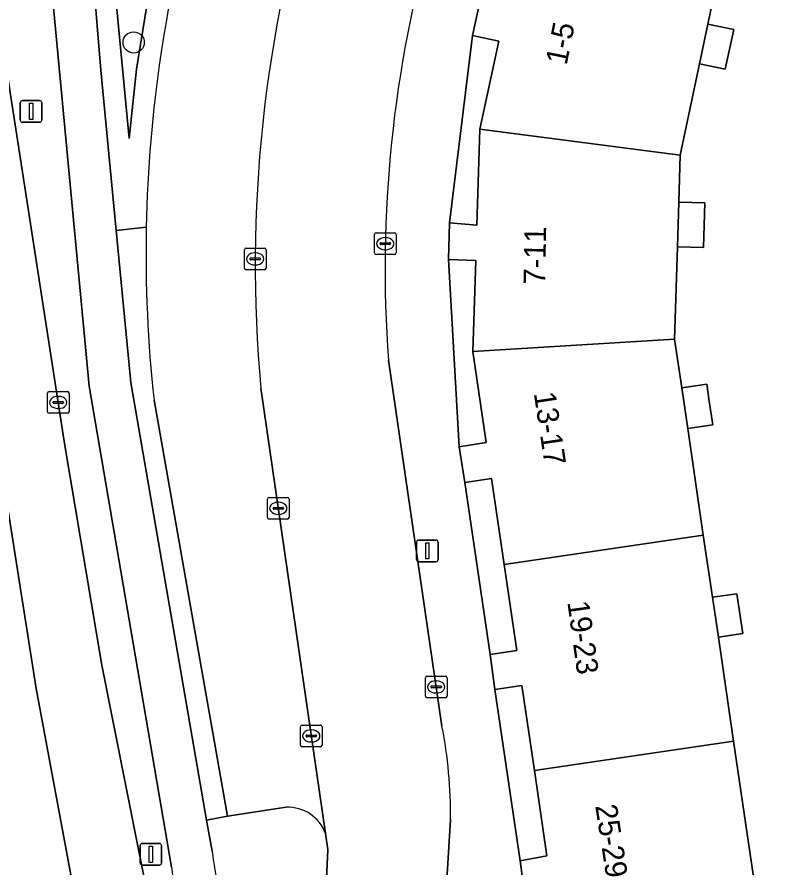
# Model space of a CAD drawing. Extents: x 159371 to 159986, y 382987 to 383597.
# Drawn here: x 159397.8 to 159432.71, y 383349.64 to 383388.85 of the extents above; entities that cross this region are included whole.
import ezdxf

# ---------------------------------------------------------------- set-up
doc = ezdxf.new("R2010")
doc.units = 0
for name, color, linetype in [('IMGEO_Boom', 7, 'Continuous'), ('IMGEO_Erf', 7, 'Continuous'), ('IMGEO_Fietspad_open', 7, 'Continuous'), ('IMGEO_Groenvoorziening', 7, 'Continuous'), ('IMGEO_Kolk', 7, 'Continuous'), ('IMGEO_Lichtmast', 7, 'Continuous'), ('IMGEO_Pand', 7, 'Continuous'), ('IMGEO_Pand_nummerreeks', 7, 'Continuous'), ('IMGEO_Parkeervlak_open', 7, 'Continuous'), ('IMGEO_Rijbaan_lokaal_open', 7, 'Continuous'), ('IMGEO_Rijbaan_regionaal_gesloten', 7, 'Continuous'), ('IMGEO_Verkeerseiland_groen', 7, 'Continuous'), ('IMGEO_Verkeerseiland_open', 7, 'Continuous'), ('IMGEO_Verkeersregelinstallatiepaal', 7, 'Continuous'), ('IMGEO_Voetpad_open', 7, 'Continuous')]:
    doc.layers.add(name, color=color, linetype=linetype)

msp = doc.modelspace()

# ---------------------------------------------------------------- linework, layer by layer
at = {"layer": 'IMGEO_Boom'}
msp.add_circle((159403.177, 383387.674), 0.489, dxfattribs=at)
at = {"layer": 'IMGEO_Erf'}
msp.add_lwpolyline([(159430.16, 383390.86), (159429.667, 383388.524), (159430.854, 383388.274), (159430.467, 383386.44), (159429.28, 383386.69), (159428.392, 383382.479), (159428.324, 383380.313), (159429.522, 383380.275), (159429.457, 383378.217), (159428.259, 383378.255), (159428.125, 383373.99), (159428.456, 383371.738), (159429.615, 383371.909), (159429.73, 383371.126), (159429.891, 383370.032), (159428.732, 383369.862), (159429.453, 383364.954), (159429.875, 383362.082), (159431.003, 383362.248), (159431.274, 383360.406), (159430.146, 383360.24), (159430.851, 383355.442), (159432.244, 383345.961), (159433.639, 383336.466)], dxfattribs=at)
at = {"layer": 'IMGEO_Fietspad_open'}
for points in [[(159398.117, 383396.756), (159399.119, 383392.769), (159399.173, 383392.556), (159401.123, 383371.822), (159404.915, 383349.644)], [(159406.791, 383350.369), (159406.542, 383351.805), (159403.042, 383371.984), (159402.373, 383379.003), (159401.668, 383386.401), (159400.956, 383394.962)]]:
    msp.add_lwpolyline(points, dxfattribs=at)
for centre, radius, start, end in [((159440.077, 383355.21), 33.636, 188.2744, 198.5159), ((159443.982, 383355.971), 39.576, 189.1999, 197.6695)]:
    msp.add_arc(centre, radius, start, end, dxfattribs=at)
at = {"layer": 'IMGEO_Groenvoorziening'}
msp.add_lwpolyline([(159419.94, 383400.506), (159420.009, 383400.664), (159408.921, 383404.193), (159405.054, 383399.714), (159400.956, 383394.962), (159401.668, 383386.401), (159402.373, 383379.003), (159403.759, 383379.151)], dxfattribs=at)
for points in [[(159417.737, 383398.308), (159418.48, 383399.91), (159409.013, 383402.804), (159401.894, 383394.566), (159402.974, 383383.238), (159403.31, 383386.448), (159403.787, 383389.376), (159404.473, 383392.564), (159406.076, 383398.462), (159416.727, 383395.545)], [(159406.076, 383398.462), (159404.473, 383392.564), (159403.787, 383389.376), (159403.31, 383386.448), (159402.974, 383383.238), (159401.894, 383394.566), (159409.013, 383402.804), (159418.48, 383399.91), (159417.737, 383398.308), (159416.727, 383395.545)]]:
    msp.add_lwpolyline(points, close=True, dxfattribs=at)
msp.add_arc((159465.951, 383377.929), 62.204, 164.11625, 178.874, dxfattribs=at)
at = {"layer": 'IMGEO_Kolk'}
for p, q in [((159414.283, 383377.967), (159414.283, 383378.819)), ((159414.358, 383378.893), (159415.21, 383378.893)), ((159414.771, 383378.673), (159414.796, 383378.673)), ((159415.284, 383378.819), (159415.284, 383377.967)), ((159408.359, 383378.19), (159409.211, 383378.19)), ((159414.542, 383378.387), (159414.542, 383378.399)), ((159414.98, 383378.35), (159414.582, 383378.35)), ((159414.585, 383378.436), (159414.983, 383378.436)), ((159415.026, 383378.399), (159415.026, 383378.387)), ((159408.284, 383377.264), (159408.284, 383378.116)), ((159408.772, 383377.97), (159408.797, 383377.97)), ((159409.285, 383378.116), (159409.285, 383377.264)), ((159415.21, 383377.893), (159414.358, 383377.893)), ((159414.794, 383378.113), (159414.769, 383378.113)), ((159408.543, 383377.684), (159408.543, 383377.696)), ((159408.981, 383377.647), (159408.583, 383377.647)), ((159408.586, 383377.733), (159408.984, 383377.733)), ((159408.795, 383377.41), (159408.77, 383377.41)), ((159409.027, 383377.696), (159409.027, 383377.684)), ((159409.211, 383377.19), (159408.359, 383377.19)), ((159399.197, 383370.645), (159399.197, 383371.497)), ((159399.272, 383371.571), (159400.124, 383371.571)), ((159400.198, 383371.497), (159400.198, 383370.645)), ((159399.499, 383371.114), (159399.897, 383371.114)), ((159399.685, 383371.351), (159399.71, 383371.351)), ((159399.456, 383371.065), (159399.456, 383371.077)), ((159399.894, 383371.028), (159399.496, 383371.028)), ((159399.708, 383370.791), (159399.683, 383370.791)), ((159399.94, 383371.077), (159399.94, 383371.065)), ((159400.124, 383370.571), (159399.272, 383370.571)), ((159409.347, 383365.763), (159409.347, 383366.615)), ((159409.422, 383366.689), (159410.274, 383366.689)), ((159409.835, 383366.469), (159409.86, 383366.469)), ((159410.348, 383366.615), (159410.348, 383365.763)), ((159409.606, 383366.183), (159409.606, 383366.195)), ((159410.044, 383366.146), (159409.646, 383366.146)), ((159409.649, 383366.232), (159410.047, 383366.232)), ((159410.09, 383366.195), (159410.09, 383366.183)), ((159410.274, 383365.689), (159409.422, 383365.689)), ((159409.858, 383365.909), (159409.833, 383365.909)), ((159416.633, 383357.524), (159416.633, 383358.376)), ((159416.708, 383358.45), (159417.56, 383358.45)), ((159417.121, 383358.23), (159417.146, 383358.23)), ((159417.634, 383358.376), (159417.634, 383357.524)), ((159416.892, 383357.944), (159416.892, 383357.956)), ((159417.33, 383357.907), (159416.932, 383357.907)), ((159416.935, 383357.993), (159417.333, 383357.993)), ((159417.376, 383357.956), (159417.376, 383357.944)), ((159417.56, 383357.45), (159416.708, 383357.45)), ((159417.144, 383357.67), (159417.119, 383357.67)), ((159410.869, 383355.263), (159410.869, 383356.115)), ((159410.944, 383356.189), (159411.796, 383356.189)), ((159411.357, 383355.969), (159411.382, 383355.969)), ((159411.87, 383356.115), (159411.87, 383355.263)), ((159411.128, 383355.683), (159411.128, 383355.695)), ((159411.566, 383355.646), (159411.168, 383355.646)), ((159411.171, 383355.732), (159411.569, 383355.732)), ((159411.612, 383355.695), (159411.612, 383355.683)), ((159411.796, 383355.189), (159410.944, 383355.189)), ((159411.38, 383355.409), (159411.355, 383355.409))]:
    msp.add_line(p, q, dxfattribs=at)
for points in [[(159414.283, 383377.967), (159414.283, 383378.819)], [(159414.358, 383378.893), (159415.21, 383378.893)], [(159415.284, 383378.819), (159415.284, 383377.967)], [(159408.359, 383378.19), (159409.211, 383378.19)], [(159408.284, 383377.264), (159408.284, 383378.116)], [(159409.285, 383378.116), (159409.285, 383377.264)], [(159415.21, 383377.893), (159414.358, 383377.893)], [(159409.211, 383377.19), (159408.359, 383377.19)], [(159399.197, 383370.645), (159399.197, 383371.497)], [(159399.272, 383371.571), (159400.124, 383371.571)], [(159400.198, 383371.497), (159400.198, 383370.645)], [(159400.124, 383370.571), (159399.272, 383370.571)], [(159409.347, 383365.763), (159409.347, 383366.615)], [(159409.422, 383366.689), (159410.274, 383366.689)], [(159410.348, 383366.615), (159410.348, 383365.763)], [(159410.274, 383365.689), (159409.422, 383365.689)], [(159416.633, 383357.524), (159416.633, 383358.376)], [(159416.708, 383358.45), (159417.56, 383358.45)], [(159417.634, 383358.376), (159417.634, 383357.524)], [(159417.56, 383357.45), (159416.708, 383357.45)], [(159410.869, 383355.263), (159410.869, 383356.115)], [(159410.944, 383356.189), (159411.796, 383356.189)], [(159411.87, 383356.115), (159411.87, 383355.263)], [(159411.796, 383355.189), (159410.944, 383355.189)]]:
    msp.add_lwpolyline(points, dxfattribs=at)
for centre, radius, start, end in [((159414.36, 383378.817), 0.0765, 91.552, 178.448), ((159414.36, 383378.817), 0.0765, 91.552, 178.448), ((159415.208, 383378.817), 0.0765, 1.552, 88.448), ((159415.208, 383378.817), 0.0765, 1.552, 88.448), ((159408.361, 383378.114), 0.0765, 91.552, 178.448), ((159408.361, 383378.114), 0.0765, 91.552, 178.448), ((159409.209, 383378.114), 0.0765, 1.552, 88.448), ((159409.209, 383378.114), 0.0765, 1.552, 88.448), ((159414.582, 383378.396), 0.0403, 85.8775, 175.7526), ((159414.579, 383378.386), 0.0366, 178.938, 274.7102), ((159414.983, 383378.393), 0.043, 264.8664, 352.4533), ((159414.987, 383378.398), 0.0386, 1.7309, 96.639), ((159414.36, 383377.969), 0.0765, 181.552, 268.448), ((159414.36, 383377.969), 0.0765, 181.552, 268.448), ((159415.208, 383377.969), 0.0765, 271.552, 358.448), ((159415.208, 383377.969), 0.0765, 271.552, 358.448), ((159408.583, 383377.693), 0.0403, 85.8775, 175.7526), ((159408.58, 383377.683), 0.0366, 178.938, 274.7102), ((159408.984, 383377.69), 0.043, 264.8664, 352.4533), ((159408.988, 383377.695), 0.0386, 1.7309, 96.639), ((159408.361, 383377.266), 0.0765, 181.552, 268.448), ((159408.361, 383377.266), 0.0765, 181.552, 268.448), ((159409.209, 383377.266), 0.0765, 271.552, 358.448), ((159409.209, 383377.266), 0.0765, 271.552, 358.448), ((159399.274, 383371.495), 0.0765, 91.552, 178.448), ((159399.274, 383371.495), 0.0765, 91.552, 178.448), ((159400.122, 383371.495), 0.0765, 1.552, 88.448), ((159400.122, 383371.495), 0.0765, 1.552, 88.448), ((159399.496, 383371.074), 0.0403, 85.8775, 175.7526), ((159399.901, 383371.076), 0.0386, 1.7309, 96.639), ((159399.493, 383371.064), 0.0366, 178.938, 274.7102), ((159399.897, 383371.071), 0.043, 264.8664, 352.4533), ((159399.274, 383370.647), 0.0765, 181.552, 268.448), ((159399.274, 383370.647), 0.0765, 181.552, 268.448), ((159400.122, 383370.647), 0.0765, 271.552, 358.448), ((159400.122, 383370.647), 0.0765, 271.552, 358.448), ((159409.424, 383366.613), 0.0765, 91.552, 178.448), ((159409.424, 383366.613), 0.0765, 91.552, 178.448), ((159410.272, 383366.613), 0.0765, 1.552, 88.448), ((159410.272, 383366.613), 0.0765, 1.552, 88.448), ((159409.646, 383366.192), 0.0403, 85.8775, 175.7526), ((159409.643, 383366.182), 0.0366, 178.938, 274.7102), ((159410.047, 383366.189), 0.043, 264.8664, 352.4533), ((159410.051, 383366.194), 0.0386, 1.7309, 96.639), ((159409.424, 383365.765), 0.0765, 181.552, 268.448), ((159409.424, 383365.765), 0.0765, 181.552, 268.448), ((159410.272, 383365.765), 0.0765, 271.552, 358.448), ((159410.272, 383365.765), 0.0765, 271.552, 358.448), ((159416.71, 383358.374), 0.0765, 91.552, 178.448), ((159416.71, 383358.374), 0.0765, 91.552, 178.448), ((159417.558, 383358.374), 0.0765, 1.552, 88.448), ((159417.558, 383358.374), 0.0765, 1.552, 88.448), ((159416.932, 383357.953), 0.0403, 85.8775, 175.7526), ((159416.929, 383357.943), 0.0366, 178.938, 274.7102), ((159417.333, 383357.95), 0.043, 264.8664, 352.4533), ((159417.337, 383357.955), 0.0386, 1.7309, 96.639), ((159416.71, 383357.526), 0.0765, 181.552, 268.448), ((159416.71, 383357.526), 0.0765, 181.552, 268.448), ((159417.558, 383357.526), 0.0765, 271.552, 358.448), ((159417.558, 383357.526), 0.0765, 271.552, 358.448), ((159410.946, 383356.113), 0.0765, 91.552, 178.448), ((159410.946, 383356.113), 0.0765, 91.552, 178.448), ((159411.794, 383356.113), 0.0765, 1.552, 88.448), ((159411.794, 383356.113), 0.0765, 1.552, 88.448), ((159411.168, 383355.692), 0.0403, 85.8775, 175.7526), ((159411.165, 383355.682), 0.0366, 178.938, 274.7102), ((159411.569, 383355.689), 0.043, 264.8664, 352.4533), ((159411.573, 383355.694), 0.0386, 1.7309, 96.639), ((159410.946, 383355.265), 0.0765, 181.552, 268.448), ((159410.946, 383355.265), 0.0765, 181.552, 268.448), ((159411.794, 383355.265), 0.0765, 271.552, 358.448), ((159411.794, 383355.265), 0.0765, 271.552, 358.448)]:
    msp.add_arc(centre, radius, start, end, dxfattribs=at)
for centre, major_axis, ratio, start_param, end_param in [((159414.77, 383378.393), (-0.387, 0.002), 0.722429, 4.712389, 7.853982), ((159414.795, 383378.393), (-0.39, 0.002), 0.717154, 1.570796, 4.712389), ((159408.771, 383377.69), (-0.387, 0.002), 0.722429, 4.712389, 7.853982), ((159408.796, 383377.69), (-0.39, 0.002), 0.717154, 1.570796, 4.712389), ((159399.684, 383371.071), (-0.387, 0.002), 0.722429, 4.712389, 7.853982), ((159399.709, 383371.071), (-0.39, 0.002), 0.717154, 1.570796, 4.712389), ((159409.834, 383366.189), (-0.387, 0.002), 0.722429, 4.712389, 7.853982), ((159409.859, 383366.189), (-0.39, 0.002), 0.717154, 1.570796, 4.712389), ((159417.12, 383357.95), (-0.387, 0.002), 0.722429, 4.712389, 7.853982), ((159417.145, 383357.95), (-0.39, 0.002), 0.717154, 1.570796, 4.712389), ((159411.356, 383355.689), (-0.387, 0.002), 0.722429, 4.712389, 7.853982), ((159411.381, 383355.689), (-0.39, 0.002), 0.717154, 1.570796, 4.712389)]:
    msp.add_ellipse(centre, major_axis=major_axis, ratio=ratio, start_param=start_param, end_param=end_param, dxfattribs=at)
at = {"layer": 'IMGEO_Lichtmast'}
for p, q in [((159416.227, 383363.825), (159416.227, 383364.625)), ((159416.227, 383364.625), (159416.227, 383363.825)), ((159416.327, 383364.725), (159417.117, 383364.725)), ((159417.117, 383364.725), (159416.327, 383364.725)), ((159417.217, 383364.625), (159417.217, 383363.825)), ((159417.217, 383363.825), (159417.217, 383364.625)), ((159417.117, 383363.725), (159416.327, 383363.725)), ((159416.327, 383363.725), (159417.117, 383363.725)), ((159403.575, 383350.732), (159404.365, 383350.732)), ((159404.365, 383350.732), (159403.575, 383350.732)), ((159403.475, 383349.832), (159403.475, 383350.632)), ((159403.475, 383350.632), (159403.475, 383349.832)), ((159404.465, 383350.632), (159404.465, 383349.832)), ((159404.465, 383349.832), (159404.465, 383350.632)), ((159404.365, 383349.732), (159403.575, 383349.732)), ((159403.575, 383349.732), (159404.365, 383349.732))]:
    msp.add_line(p, q, dxfattribs=at)
for points in [[(159416.647, 383364.6), (159416.797, 383364.6), (159416.797, 383363.85), (159416.647, 383363.85), (159416.647, 383364.6)], [(159403.895, 383350.607), (159404.045, 383350.607), (159404.045, 383349.857), (159403.895, 383349.857), (159403.895, 383350.607)]]:
    msp.add_lwpolyline(points, dxfattribs=at)
for centre, start, end in [((159416.327, 383364.625), 90, 180), ((159416.327, 383364.625), 90, 180), ((159417.117, 383364.625), 0, 90), ((159417.117, 383364.625), 360, 90), ((159416.327, 383363.825), 180, 270), ((159416.327, 383363.825), 180, 270), ((159417.117, 383363.825), 270, 0), ((159417.117, 383363.825), 270, 0), ((159403.575, 383350.632), 90, 180), ((159403.575, 383350.632), 90, 180), ((159404.365, 383350.632), 0, 90), ((159404.365, 383350.632), 360, 90), ((159403.575, 383349.832), 180, 270), ((159403.575, 383349.832), 180, 270), ((159404.365, 383349.832), 270, 0), ((159404.365, 383349.832), 270, 0)]:
    msp.add_arc(centre, 0.1, start, end, dxfattribs=at)
at = {"layer": 'IMGEO_Pand'}
for points in [[(159429.667, 383388.524), (159430.16, 383390.86), (159421.274, 383393.617), (159420.365, 383389.357), (159419.157, 383389.616), (159418.808, 383387.99), (159420.018, 383387.732), (159419.151, 383383.672), (159428.392, 383382.479), (159429.28, 383386.69)], [(159429.667, 383388.524), (159429.28, 383386.69), (159430.467, 383386.44), (159430.854, 383388.274)], [(159428.259, 383378.255), (159428.324, 383380.313), (159428.392, 383382.479), (159419.151, 383383.672), (159419.007, 383379.247), (159417.747, 383379.347), (159417.702, 383377.663), (159418.954, 383377.622), (159418.817, 383373.426), (159428.125, 383373.99)], [(159428.324, 383380.313), (159428.259, 383378.255), (159429.457, 383378.217), (159429.522, 383380.275)], [(159428.732, 383369.862), (159428.456, 383371.738), (159428.125, 383373.99), (159418.817, 383373.426), (159419.435, 383369.226), (159418.193, 383369.018), (159418.452, 383367.384), (159419.68, 383367.565), (159420.263, 383363.601), (159429.453, 383364.954)], [(159428.456, 383371.738), (159428.732, 383369.862), (159429.891, 383370.032), (159429.73, 383371.126), (159429.615, 383371.909)], [(159430.146, 383360.24), (159429.875, 383362.082), (159429.453, 383364.954), (159420.263, 383363.601), (159420.847, 383359.637), (159419.625, 383359.444), (159419.844, 383357.834), (159421.085, 383358.017), (159421.663, 383354.089), (159430.851, 383355.442)], [(159429.875, 383362.082), (159430.146, 383360.24), (159431.274, 383360.406), (159431.003, 383362.248)], [(159423.058, 383344.608), (159432.244, 383345.961), (159430.851, 383355.442), (159421.663, 383354.089), (159422.241, 383350.162), (159421.005, 383349.935), (159421.227, 383348.338), (159422.482, 383348.523)]]:
    msp.add_lwpolyline(points, close=True, dxfattribs=at)
at = {"layer": 'IMGEO_Parkeervlak_open'}
for points in [[(159412.023, 383351.193), (159409.047, 383371.727)], [(159404.116, 383371.169), (159407.502, 383351.986), (159410.209, 383352.398)]]:
    msp.add_lwpolyline(points, dxfattribs=at)
for centre, radius, start, end in [((159470.721, 383377.412), 61.935, 162.62365, 185.26683), ((159465.951, 383377.929), 62.204, 164.11625, 178.874), ((159465.845, 383377.929), 62.098, 178.87228, 186.24949), ((159410.293, 383350.557), 1.843, 20.1973, 92.6123)]:
    msp.add_arc(centre, radius, start, end, dxfattribs=at)
at = {"layer": 'IMGEO_Rijbaan_lokaal_open'}
for points in [[(159417.399, 383356.141), (159414.932, 383373.02)], [(159409.047, 383371.727), (159412.023, 383351.193), (159412.13, 383350.455), (159411.991, 383347.386)], [(159411.128, 383341.348), (159417.091, 383340.199), (159417.439, 383345.986), (159417.791, 383351.83)]]:
    msp.add_lwpolyline(points, dxfattribs=at)
for centre, radius, start, end in [((159470.721, 383377.412), 61.935, 162.62365, 185.26683), ((159471.546, 383377.261), 56.772, 163.9766, 184.2843), ((159396.522, 383352.069), 21.27, 359.3552, 11.036)]:
    msp.add_arc(centre, radius, start, end, dxfattribs=at)
at = {"layer": 'IMGEO_Rijbaan_regionaal_gesloten'}
for points in [[(159403.9, 383347.897), (159401.71, 383358.95), (159399.992, 383369.176), (159399.696, 383371.074), (159396.728, 383390.154), (159393.91, 383388.103), (159394.285, 383385.736), (159398.684, 383357.88), (159401.833, 383340.927)], [(159421.088, 383273.781), (159415.124, 383292.413), (159412.518, 383300.689), (159411.115, 383305.269), (159409.091, 383311.769), (159407.402, 383318.032), (159405.305, 383327.063), (159401.833, 383340.927), (159398.684, 383357.88), (159394.285, 383385.736), (159393.91, 383388.103), (159391.102, 383386.058), (159392.136, 383379.485), (159394.586, 383364.232), (159396.636, 383352.03), (159398.985, 383340.227), (159401.734, 383327.224), (159405.034, 383314.472), (159415.383, 383281.415), (159427.53, 383243.457)]]:
    msp.add_lwpolyline(points, dxfattribs=at)
at = {"layer": 'IMGEO_Verkeerseiland_groen'}
for points in [[(159410.209, 383352.398), (159407.502, 383351.986), (159406.542, 383351.805), (159406.791, 383350.369)], [(159411.991, 383347.386), (159412.13, 383350.455), (159412.023, 383351.193)]]:
    msp.add_lwpolyline(points, dxfattribs=at)
for centre, radius, start, end in [((159410.293, 383350.557), 1.843, 20.1973, 92.6123), ((159440.077, 383355.21), 33.636, 188.2744, 198.5159)]:
    msp.add_arc(centre, radius, start, end, dxfattribs=at)
at = {"layer": 'IMGEO_Verkeerseiland_open'}
msp.add_lwpolyline([(159404.915, 383349.644), (159401.123, 383371.822), (159399.173, 383392.556), (159399.119, 383392.769), (159396.728, 383390.154), (159399.696, 383371.074), (159399.992, 383369.176), (159401.71, 383358.95), (159403.9, 383347.897), (159404.263, 383345.982), (159404.796, 383344.107), (159405.493, 383342.287), (159406.351, 383340.537), (159407.157, 383339.182), (159407.29, 383339.017)], dxfattribs=at)
msp.add_arc((159443.982, 383355.971), 39.576, 189.1999, 197.6695, dxfattribs=at)
at = {"layer": 'IMGEO_Verkeersregelinstallatiepaal'}
for p, q in [((159397.949, 383384.092), (159397.949, 383384.892)), ((159397.949, 383384.892), (159397.949, 383384.092)), ((159398.049, 383384.992), (159398.839, 383384.992)), ((159398.839, 383384.992), (159398.049, 383384.992)), ((159398.939, 383384.892), (159398.939, 383384.092)), ((159398.939, 383384.092), (159398.939, 383384.892)), ((159398.839, 383383.992), (159398.049, 383383.992)), ((159398.049, 383383.992), (159398.839, 383383.992))]:
    msp.add_line(p, q, dxfattribs=at)
msp.add_lwpolyline([(159398.369, 383384.867), (159398.519, 383384.867), (159398.519, 383384.117), (159398.369, 383384.117), (159398.369, 383384.867)], dxfattribs=at)
for centre, start, end in [((159398.049, 383384.892), 90, 180), ((159398.049, 383384.892), 90, 180), ((159398.839, 383384.892), 0, 90), ((159398.839, 383384.892), 360, 90), ((159398.049, 383384.092), 180, 270), ((159398.049, 383384.092), 180, 270), ((159398.839, 383384.092), 270, 0), ((159398.839, 383384.092), 270, 0)]:
    msp.add_arc(centre, 0.1, start, end, dxfattribs=at)
at = {"layer": 'IMGEO_Voetpad_open'}
for points in [[(159439.418, 383279.733), (159438.838, 383281.521), (159436.438, 383288.932), (159435.858, 383290.72), (159433.471, 383298.094), (159432.891, 383299.882), (159430.519, 383307.208), (159429.939, 383308.996), (159427.555, 383316.36), (159426.975, 383318.148), (159424.021, 383329.385), (159423.804, 383331.003), (159422.633, 383338.865), (159422.397, 383340.483), (159421.227, 383348.338), (159421.005, 383349.935), (159419.844, 383357.834), (159419.625, 383359.444), (159418.452, 383367.384), (159418.193, 383369.018), (159417.702, 383377.663), (159417.747, 383379.347), (159418.808, 383387.99), (159419.157, 383389.616)], [(159403.759, 383379.151), (159402.373, 383379.003), (159403.042, 383371.984), (159406.542, 383351.805), (159407.502, 383351.986), (159404.116, 383371.169)], [(159414.932, 383373.02), (159417.399, 383356.141)], [(159417.791, 383351.83), (159417.439, 383345.986)]]:
    msp.add_lwpolyline(points, dxfattribs=at)
for points in [[(159417.747, 383379.347), (159419.007, 383379.247), (159419.151, 383383.672), (159420.018, 383387.732), (159418.808, 383387.99)], [(159418.193, 383369.018), (159419.435, 383369.226), (159418.817, 383373.426), (159418.954, 383377.622), (159417.702, 383377.663)], [(159419.625, 383359.444), (159420.847, 383359.637), (159420.263, 383363.601), (159419.68, 383367.565), (159418.452, 383367.384)], [(159421.005, 383349.935), (159422.241, 383350.162), (159421.663, 383354.089), (159421.085, 383358.017), (159419.844, 383357.834)]]:
    msp.add_lwpolyline(points, close=True, dxfattribs=at)
for centre, radius, start, end in [((159471.546, 383377.261), 56.772, 163.9766, 184.2843), ((159465.845, 383377.929), 62.098, 178.87228, 186.24949), ((159396.522, 383352.069), 21.27, 359.3552, 11.036)]:
    msp.add_arc(centre, radius, start, end, dxfattribs=at)

# ---------------------------------------------------------------- texts
at = {"layer": 'IMGEO_Pand_nummerreeks'}
for s, rotation, p in [('1-5', 78.4723, (159423.146, 383386.595)), ('7-11', 88.9116, (159422.156, 383376.5)), ('13-17', 278.5426, (159421.632, 383371.493)), ('19-23', 277.8379, (159423.179, 383361.861)), ('25-29', 278.7641, (159424.466, 383352.469))]:
    msp.add_text(s, height=1, rotation=rotation, dxfattribs=at).set_placement(p)

doc.saveas('drawing.dxf')
